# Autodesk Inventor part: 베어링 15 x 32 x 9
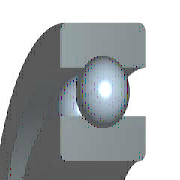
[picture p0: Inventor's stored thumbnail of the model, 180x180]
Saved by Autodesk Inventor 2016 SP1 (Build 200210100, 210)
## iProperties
IsCustomPart: 0
Created: 2012-02
Part Number: 베어링 15 x 32 x 9
Material: 강철, 연강
Description: 깊은 그루브 볼 베어링
Document SubType Name: Modeling
Standard: KS B 2023
Designer: mduedu
Standards Organization: KS
Language: ko-KR
Size Designation: 6002 - 15 x 32 x 9
Categories: <MemberInstance><Categories><Category DisplayName="샤프트 부품" InternalName="7f7aeb1f-a693-4053-b835-cee3144e0d98" Mnemonic="SHFT"><Category DisplayName="베어링" Inter
Density: 1 g/cm^3
Appearance: 노란색
Author: mduedu
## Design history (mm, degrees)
sketch "스케치" dims "d0" = 4.42 (= -0.26 x WD + 0.26 x BD)
  geometry: L1 (2.29, 11.75)-(6.71, 11.75); L2 (4.5, 11.75)-(4.5, 9.54); L3 (4.5, 11.75)-(4.5, 13.96); L4 (2.858, 10.271)-(0, 10.271); L5 (0, 7.5)-(9, 7.5); L6 (2.858, 13.229)-(0, 13.229); L7 (0, 16)-(9, 16); L8 (9, 7.5)-(9, 10.271); L9 (6.142, 10.271)-(9, 10.271); L10 (6.142, 13.229)-(9, 13.229); L11 (9, 16)-(9, 13.229); L12 (-1.4, 0)-(8.4, 0) reference; L13 (0, -0.3)-(0, 5.3) reference
  constraints: 22 end point, 4 point on line, 2 collinear, 2 perpendicular, 2 symmetric about line, 1 midpoint, 1 parallel, 14 other
  dimensions: "d9" = 15 diameter of L5 L12 (= WD); "d11" = 32 diameter of L7 L12 (= BD); "d12" = 9 distance between parallel lines of L8 L13 (= KB); "d13" = 20.542 diameter of L9 L12 (= 0.326 x BD + 0.674 x WD)
revolve "본체" stored, may be unused: angle "d6" = 90 deg
revolve "볼" stored, may be unused: angle "d7" = 90 deg
pattern_circular "IDS_ARRAYBALL[SIMPL:T]" dims angle "d3" = 360 deg
body "Solid1"
fillet "모깎기1" dims "d1" = 0.3 (= KRS)
other parameters: "WD" = 15 [user parameter; used in 5 equation terms], "BD" = 32 [user parameter; used in 5 equation terms], "KB" = 9 [user parameter; used in 1 equation term], "KRS" = 0.3 [user parameter; used in 1 equation term], "d4" = 0, "d5" = 0, "d8" = 0, "d14" = 0, "d15" = 0, "BBA" = 0 [user parameter], "BC0" = 2850000 [user parameter], "BC" = 5590000 [user parameter], "BR" = 16 (= 0.5 x BD) [user parameter], "WR" = 7.5 (= 0.5 x WD) [user parameter]
